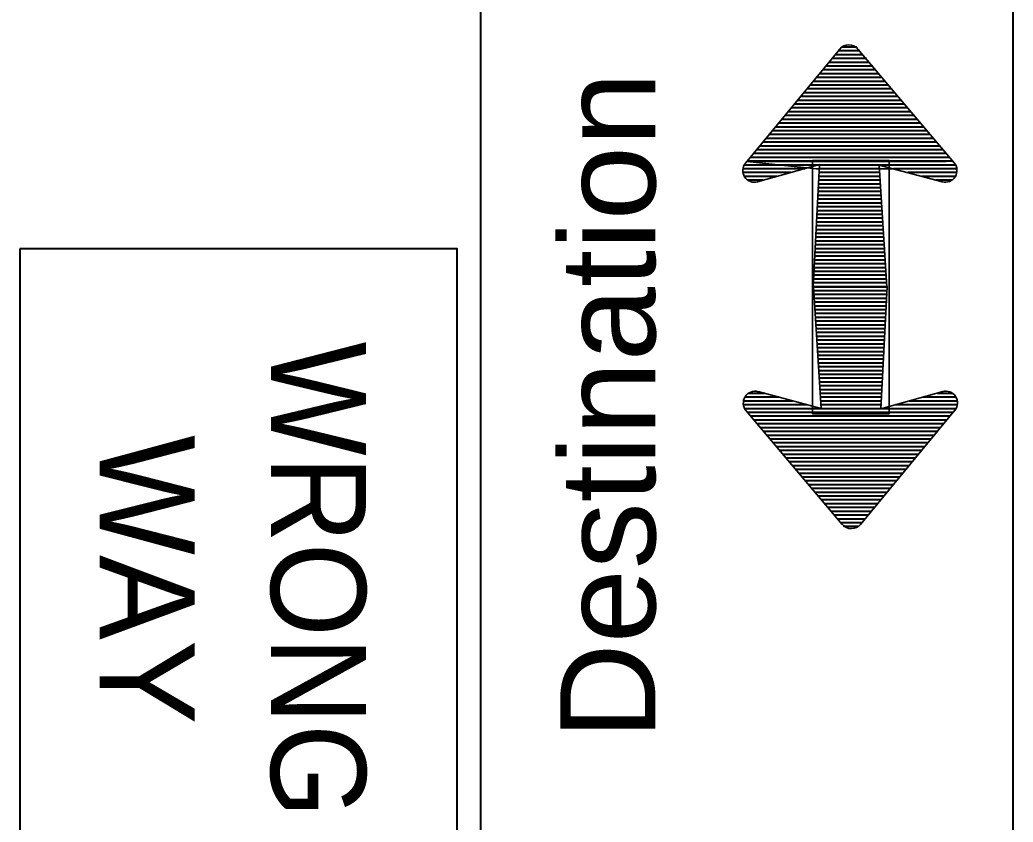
# Model space of a CAD drawing. Extents: x 1081 to 1936, y -630 to -24.
# Drawn here: x 1877.67 to 1909.01, y -170.57 to -145.26 of the extents above; entities that cross this region are included whole.
import ezdxf
from ezdxf.enums import TextEntityAlignment as Align

# ---------------------------------------------------------------- set-up
doc = ezdxf.new("R2010")
doc.units = 0
doc.layers.add('1', color=7, linetype='Continuous', lineweight=53)

msp = doc.modelspace()

# ---------------------------------------------------------------- linework, layer by layer
at = {"layer": '1', "lineweight": 40}
for p, q in [((1909.01, -173.414), (1909.01, -133.607)), ((1904.27, -146.36), (1903.394, -146.36)), ((1903.886, -146.36), (1903.394, -146.36)), ((1904.174, -146.24), (1903.49, -146.24)), ((1903.886, -146.24), (1903.49, -146.24)), ((1904.474, -146.6), (1903.202, -146.6)), ((1903.886, -146.6), (1903.202, -146.6)), ((1904.378, -146.48), (1903.298, -146.48)), ((1903.886, -146.48), (1903.298, -146.48)), ((1904.774, -146.96), (1902.902, -146.96)), ((1903.886, -146.96), (1902.902, -146.96)), ((1904.678, -146.84), (1902.998, -146.84)), ((1903.886, -146.84), (1902.998, -146.84)), ((1904.582, -146.72), (1903.094, -146.72)), ((1903.886, -146.72), (1903.094, -146.72)), ((1904.966, -147.2), (1902.698, -147.2)), ((1903.886, -147.2), (1902.698, -147.2)), ((1904.87, -147.08), (1902.794, -147.08)), ((1903.886, -147.08), (1902.794, -147.08)), ((1905.278, -147.56), (1902.398, -147.56)), ((1903.886, -147.56), (1902.398, -147.56)), ((1905.17, -147.44), (1902.506, -147.44)), ((1903.886, -147.44), (1902.506, -147.44)), ((1905.074, -147.32), (1902.602, -147.32)), ((1903.886, -147.32), (1902.602, -147.32)), ((1905.578, -147.92), (1902.11, -147.92)), ((1903.886, -147.92), (1902.11, -147.92)), ((1905.482, -147.8), (1902.206, -147.8)), ((1903.886, -147.8), (1902.206, -147.8)), ((1905.374, -147.68), (1902.302, -147.68)), ((1903.886, -147.68), (1902.302, -147.68)), ((1905.782, -148.16), (1901.906, -148.16)), ((1903.886, -148.16), (1901.906, -148.16)), ((1905.686, -148.04), (1902.002, -148.04)), ((1903.886, -148.04), (1902.002, -148.04)), ((1906.094, -148.52), (1901.606, -148.52)), ((1903.886, -148.52), (1901.606, -148.52)), ((1905.986, -148.4), (1901.714, -148.4)), ((1903.886, -148.4), (1901.714, -148.4)), ((1905.89, -148.28), (1901.81, -148.28)), ((1903.886, -148.28), (1901.81, -148.28)), ((1906.286, -148.76), (1901.414, -148.76)), ((1903.886, -148.76), (1901.414, -148.76)), ((1906.19, -148.64), (1901.51, -148.64)), ((1903.886, -148.64), (1901.51, -148.64)), ((1906.598, -149.12), (1901.114, -149.12)), ((1903.886, -149.12), (1901.114, -149.12)), ((1906.49, -149), (1901.21, -149)), ((1903.886, -149), (1901.21, -149)), ((1906.394, -148.88), (1901.306, -148.88)), ((1903.886, -148.88), (1901.306, -148.88)), ((1906.898, -149.48), (1900.814, -149.48)), ((1903.886, -149.48), (1900.814, -149.48)), ((1906.802, -149.36), (1900.91, -149.36)), ((1903.886, -149.36), (1900.91, -149.36)), ((1906.694, -149.24), (1901.018, -149.24)), ((1903.886, -149.24), (1901.018, -149.24)), ((1907.102, -149.72), (1900.622, -149.72)), ((1903.886, -149.72), (1900.622, -149.72)), ((1907.006, -149.6), (1900.718, -149.6)), ((1903.886, -149.6), (1900.718, -149.6)), ((1902.434, -149.96), (1900.49, -149.96)), ((1902.434, -149.96), (1900.49, -149.96)), ((1901.99, -150.08), (1900.49, -150.08)), ((1901.99, -150.08), (1900.49, -150.08)), ((1904.81, -150.08), (1902.89, -150.08)), ((1903.886, -150.08), (1902.89, -150.08)), ((1903.886, -149.84), (1902.902, -149.84)), ((1904.798, -149.96), (1902.902, -149.96)), ((1903.886, -149.96), (1902.902, -149.96)), ((1907.234, -149.96), (1905.23, -149.96)), ((1904.822, -150.32), (1902.878, -150.32)), ((1903.886, -150.32), (1902.878, -150.32)), ((1904.834, -150.44), (1902.878, -150.44)), ((1903.886, -150.44), (1902.878, -150.44)), ((1904.81, -150.2), (1902.89, -150.2)), ((1903.886, -150.2), (1902.89, -150.2)), ((1907.186, -150.2), (1906.13, -150.2)), ((1904.834, -150.56), (1902.866, -150.56)), ((1903.886, -150.56), (1902.866, -150.56)), ((1904.846, -150.68), (1902.866, -150.68)), ((1903.886, -150.68), (1902.866, -150.68)), ((1904.87, -151.04), (1902.842, -151.04)), ((1903.886, -151.04), (1902.842, -151.04)), ((1904.846, -150.8), (1902.854, -150.8)), ((1903.886, -150.8), (1902.854, -150.8)), ((1904.858, -150.92), (1902.854, -150.92)), ((1903.886, -150.92), (1902.854, -150.92)), ((1904.87, -151.28), (1902.83, -151.28)), ((1903.886, -151.28), (1902.83, -151.28)), ((1904.87, -151.16), (1902.842, -151.16)), ((1903.886, -151.16), (1902.842, -151.16)), ((1904.882, -151.52), (1902.818, -151.52)), ((1903.886, -151.52), (1902.818, -151.52)), ((1904.894, -151.64), (1902.818, -151.64)), ((1903.886, -151.64), (1902.818, -151.64)), ((1904.882, -151.4), (1902.83, -151.4)), ((1903.886, -151.4), (1902.83, -151.4)), ((1904.906, -151.88), (1902.794, -151.88)), ((1903.886, -151.88), (1902.794, -151.88)), ((1904.918, -152), (1902.794, -152)), ((1903.886, -152), (1902.794, -152)), ((1904.906, -151.76), (1902.806, -151.76)), ((1903.886, -151.76), (1902.806, -151.76)), ((1904.918, -152.12), (1902.782, -152.12)), ((1903.886, -152.12), (1902.782, -152.12)), ((1904.93, -152.24), (1902.782, -152.24)), ((1903.886, -152.24), (1902.782, -152.24)), ((1904.954, -152.6), (1902.758, -152.6)), ((1903.886, -152.6), (1902.758, -152.6)), ((1904.942, -152.36), (1902.77, -152.36)), ((1903.886, -152.36), (1902.77, -152.36)), ((1904.942, -152.48), (1902.77, -152.48)), ((1903.886, -152.48), (1902.77, -152.48)), ((1904.966, -152.84), (1902.746, -152.84)), ((1903.886, -152.84), (1902.746, -152.84)), ((1904.966, -152.72), (1902.758, -152.72)), ((1903.886, -152.72), (1902.758, -152.72)), ((1904.978, -153.08), (1902.734, -153.08)), ((1903.886, -153.08), (1902.734, -153.08)), ((1904.99, -153.2), (1902.734, -153.2)), ((1903.886, -153.2), (1902.734, -153.2)), ((1904.978, -152.96), (1902.746, -152.96)), ((1903.886, -152.96), (1902.746, -152.96)), ((1905.014, -153.56), (1902.71, -153.56)), ((1903.886, -153.56), (1902.71, -153.56)), ((1905.002, -153.32), (1902.722, -153.32)), ((1903.886, -153.32), (1902.722, -153.32)), ((1905.002, -153.44), (1902.722, -153.44)), ((1903.886, -153.44), (1902.722, -153.44)), ((1905.026, -153.68), (1902.698, -153.68)), ((1903.886, -153.68), (1902.698, -153.68)), ((1902.708, -153.679), (1905.036, -153.679)), ((1902.72, -153.799), (1905.024, -153.799)), ((1903.848, -153.679), (1905.036, -153.679)), ((1903.848, -153.799), (1905.024, -153.799)), ((1902.732, -153.919), (1905.012, -153.919)), ((1902.732, -154.039), (1905.012, -154.039)), ((1902.744, -154.159), (1905, -154.159)), ((1903.848, -153.919), (1905.012, -153.919)), ((1903.848, -154.039), (1905.012, -154.039)), ((1903.848, -154.159), (1905, -154.159)), ((1902.756, -154.279), (1905, -154.279)), ((1902.756, -154.399), (1904.988, -154.399)), ((1902.768, -154.519), (1904.988, -154.519)), ((1903.848, -154.279), (1905, -154.279)), ((1903.848, -154.399), (1904.988, -154.399)), ((1903.848, -154.519), (1904.988, -154.519)), ((1902.768, -154.639), (1904.976, -154.639)), ((1902.78, -154.759), (1904.976, -154.759)), ((1903.848, -154.639), (1904.976, -154.639)), ((1903.848, -154.759), (1904.976, -154.759)), ((1902.792, -154.879), (1904.964, -154.879)), ((1902.792, -154.999), (1904.964, -154.999)), ((1902.804, -155.119), (1904.952, -155.119)), ((1903.848, -154.879), (1904.964, -154.879)), ((1903.848, -154.999), (1904.964, -154.999)), ((1903.848, -155.119), (1904.952, -155.119)), ((1902.816, -155.239), (1904.952, -155.239)), ((1902.816, -155.359), (1904.94, -155.359)), ((1903.848, -155.239), (1904.952, -155.239)), ((1903.848, -155.359), (1904.94, -155.359)), ((1902.828, -155.479), (1904.94, -155.479)), ((1902.828, -155.599), (1904.928, -155.599)), ((1902.84, -155.719), (1904.916, -155.719)), ((1903.848, -155.479), (1904.94, -155.479)), ((1903.848, -155.599), (1904.928, -155.599)), ((1903.848, -155.719), (1904.916, -155.719)), ((1902.852, -155.839), (1904.916, -155.839)), ((1902.852, -155.959), (1904.904, -155.959)), ((1902.864, -156.079), (1904.904, -156.079)), ((1903.848, -155.839), (1904.916, -155.839)), ((1903.848, -155.959), (1904.904, -155.959)), ((1903.848, -156.079), (1904.904, -156.079)), ((1902.864, -156.199), (1904.892, -156.199)), ((1902.864, -156.319), (1904.892, -156.319)), ((1903.848, -156.199), (1904.892, -156.199)), ((1903.848, -156.319), (1904.892, -156.319)), ((1902.876, -156.439), (1904.88, -156.439)), ((1902.888, -156.559), (1904.88, -156.559)), ((1902.888, -156.679), (1904.868, -156.679)), ((1903.848, -156.439), (1904.88, -156.439)), ((1903.848, -156.559), (1904.88, -156.559)), ((1903.848, -156.679), (1904.868, -156.679)), ((1902.9, -156.799), (1904.868, -156.799)), ((1902.9, -156.919), (1904.856, -156.919)), ((1903.848, -156.799), (1904.868, -156.799)), ((1903.848, -156.919), (1904.856, -156.919)), ((1900.548, -157.159), (1901.604, -157.159)), ((1902.912, -157.039), (1904.856, -157.039)), ((1902.924, -157.159), (1904.844, -157.159)), ((1902.924, -157.279), (1904.844, -157.279)), ((1903.848, -157.039), (1904.856, -157.039)), ((1903.848, -157.159), (1904.844, -157.159)), ((1903.848, -157.279), (1904.844, -157.279)), ((1905.744, -157.279), (1907.244, -157.279)), ((1905.744, -157.279), (1907.244, -157.279)), ((1900.5, -157.399), (1902.504, -157.399)), ((1900.632, -157.639), (1907.112, -157.639)), ((1902.936, -157.399), (1904.832, -157.399)), ((1903.848, -157.399), (1904.832, -157.399)), ((1903.848, -157.519), (1904.832, -157.519)), ((1903.848, -157.639), (1907.112, -157.639)), ((1905.3, -157.399), (1907.244, -157.399)), ((1905.3, -157.399), (1907.244, -157.399)), ((1900.728, -157.759), (1907.016, -157.759)), ((1900.836, -157.879), (1906.92, -157.879)), ((1903.848, -157.759), (1907.016, -157.759)), ((1903.848, -157.879), (1906.92, -157.879)), ((1900.932, -157.999), (1906.824, -157.999)), ((1901.04, -158.119), (1906.716, -158.119)), ((1901.136, -158.239), (1906.62, -158.239)), ((1903.848, -157.999), (1906.824, -157.999)), ((1903.848, -158.119), (1906.716, -158.119)), ((1903.848, -158.239), (1906.62, -158.239)), ((1901.244, -158.359), (1906.524, -158.359)), ((1901.34, -158.479), (1906.428, -158.479)), ((1903.848, -158.359), (1906.524, -158.359)), ((1903.848, -158.479), (1906.428, -158.479)), ((1901.448, -158.599), (1906.32, -158.599)), ((1901.544, -158.719), (1906.224, -158.719)), ((1901.64, -158.839), (1906.128, -158.839)), ((1903.848, -158.599), (1906.32, -158.599)), ((1903.848, -158.719), (1906.224, -158.719)), ((1903.848, -158.839), (1906.128, -158.839)), ((1901.748, -158.959), (1906.02, -158.959)), ((1901.844, -159.079), (1905.924, -159.079)), ((1901.952, -159.199), (1905.828, -159.199)), ((1903.848, -158.959), (1906.02, -158.959)), ((1903.848, -159.079), (1905.924, -159.079)), ((1903.848, -159.199), (1905.828, -159.199)), ((1902.048, -159.319), (1905.732, -159.319)), ((1902.156, -159.439), (1905.624, -159.439)), ((1903.848, -159.319), (1905.732, -159.319)), ((1903.848, -159.439), (1905.624, -159.439)), ((1902.252, -159.559), (1905.528, -159.559)), ((1902.36, -159.679), (1905.432, -159.679)), ((1902.456, -159.799), (1905.336, -159.799)), ((1903.848, -159.559), (1905.528, -159.559)), ((1903.848, -159.679), (1905.432, -159.679)), ((1903.848, -159.799), (1905.336, -159.799)), ((1902.564, -159.919), (1905.228, -159.919)), ((1902.66, -160.039), (1905.132, -160.039)), ((1902.768, -160.159), (1905.036, -160.159)), ((1903.848, -159.919), (1905.228, -159.919)), ((1903.848, -160.039), (1905.132, -160.039)), ((1903.848, -160.159), (1905.036, -160.159)), ((1902.864, -160.279), (1904.94, -160.279)), ((1902.96, -160.399), (1904.832, -160.399)), ((1903.848, -160.279), (1904.94, -160.279)), ((1903.848, -160.399), (1904.832, -160.399)), ((1903.056, -160.519), (1904.736, -160.519)), ((1903.152, -160.639), (1904.64, -160.639)), ((1903.26, -160.759), (1904.532, -160.759)), ((1903.848, -160.519), (1904.736, -160.519)), ((1903.848, -160.639), (1904.64, -160.639)), ((1903.848, -160.759), (1904.532, -160.759)), ((1903.356, -160.879), (1904.436, -160.879)), ((1903.464, -160.999), (1904.34, -160.999)), ((1903.848, -160.879), (1904.436, -160.879)), ((1903.848, -160.999), (1904.34, -160.999)), ((1903.56, -161.119), (1904.244, -161.119)), ((1903.848, -161.119), (1904.244, -161.119))]:
    msp.add_line(p, q, dxfattribs=at)
at = {"layer": '1', "lineweight": 35}
for p, q in [((1900.562, -149.78), (1903.538, -146.18)), ((1904.114, -146.18), (1907.15, -149.768)), ((1900.61, -149.725), (1906.898, -149.725)), ((1903.62, -161.179), (1900.584, -157.591)), ((1907.172, -157.579), (1904.196, -161.179))]:
    msp.add_line(p, q, dxfattribs=at)
at = {"layer": '1', "lineweight": 40}
for points in [[(1892.21, -173.414), (1892.21, -133.607), (1909.01, -133.607)], [(1903.886, -146.12), (1903.622, -146.12), (1903.61, -146.12)], [(1904.042, -146.12), (1904.066, -146.12), (1904.042, -146.12), (1903.622, -146.12), (1903.622, -146.12)], [(1902.866, -149.84), (1900.538, -149.84), (1900.526, -149.84)], [(1902.866, -149.84), (1900.538, -149.84), (1900.526, -149.84)], [(1907.198, -149.84), (1907.186, -149.84), (1904.786, -149.84), (1902.902, -149.84)], [(1907.234, -150.08), (1907.222, -150.08), (1905.686, -150.08)], [(1901.558, -150.2), (1900.538, -150.2), (1900.526, -150.2)], [(1901.558, -150.2), (1900.538, -150.2), (1900.526, -150.2)], [(1901.126, -150.32), (1900.646, -150.32), (1900.634, -150.32)], [(1901.126, -150.32), (1900.646, -150.32), (1900.634, -150.32)], [(1907.078, -150.32), (1907.066, -150.32), (1906.574, -150.32)], [(1900.5, -157.279), (1900.512, -157.279), (1902.048, -157.279)], [(1900.656, -157.039), (1900.668, -157.039), (1901.16, -157.039)], [(1906.176, -157.159), (1907.196, -157.159), (1907.208, -157.159)], [(1906.176, -157.159), (1907.196, -157.159), (1907.208, -157.159)], [(1906.608, -157.039), (1907.088, -157.039), (1907.1, -157.039)], [(1906.608, -157.039), (1907.088, -157.039), (1907.1, -157.039)], [(1900.536, -157.519), (1900.548, -157.519), (1902.948, -157.519), (1904.832, -157.519)], [(1904.868, -157.519), (1907.196, -157.519), (1907.208, -157.519)], [(1904.868, -157.519), (1907.196, -157.519), (1907.208, -157.519)], [(1903.692, -161.239), (1903.668, -161.239), (1903.692, -161.239), (1904.112, -161.239), (1904.112, -161.239)], [(1903.848, -161.239), (1904.112, -161.239), (1904.124, -161.239)]]:
    msp.add_lwpolyline(points, dxfattribs=at)
at = {"layer": '1', "lineweight": 35}
for points in [[(1907.09, -149.965), (1907.078, -149.965), (1904.678, -149.965), (1902.794, -149.965), (1900.61, -149.725)], [(1906.766, -150.368), (1904.786, -149.84), (1905.026, -153.68), (1902.698, -153.68), (1902.902, -149.828), (1900.946, -150.368)], [(1900.968, -156.991), (1902.948, -157.519), (1902.708, -153.679), (1905.036, -153.679), (1904.832, -157.531), (1906.788, -156.991)]]:
    msp.add_lwpolyline(points, dxfattribs=at)
msp.add_lwpolyline([(1902.682, -149.694), (1905.095, -149.694), (1905.095, -157.692), (1902.682, -157.692)], close=True, dxfattribs=at)
at = {"layer": '1', "lineweight": 40}
msp.add_lwpolyline([(1877.667, -152.489), (1877.667, -173.489), (1891.466, -173.489), (1891.466, -152.489)], close=True, dxfattribs=at)
at = {"layer": '1', "lineweight": 35}
for centre, start, end in [((1903.825, -146.418), 40.2565, 140.4047), ((1900.85, -150.013), 140.43, 285.5512), ((1906.867, -150.009), 255.1137, 40.2576), ((1900.867, -157.351), 75.1137, 220.2576), ((1906.883, -157.346), 320.43, 105.5512), ((1903.908, -160.941), 220.2565, 320.4047)]:
    msp.add_arc(centre, 0.372, start, end, dxfattribs=at)

# ---------------------------------------------------------------- texts
at = {"layer": '1'}
for s, rotation, width, p in [('Destination', 90, 1.05, (1897.719, -157.437)), ('WRONG', 270, 0.95, (1885.588, -162.928))]:
    msp.add_text(s, height=3, rotation=rotation, dxfattribs=dict(at, width=width)).set_placement(p, align=Align.CENTER)
msp.add_text('WAY', height=3, rotation=270, dxfattribs=at).set_placement((1880.188, -162.928), align=Align.CENTER)

doc.saveas('drawing.dxf')
